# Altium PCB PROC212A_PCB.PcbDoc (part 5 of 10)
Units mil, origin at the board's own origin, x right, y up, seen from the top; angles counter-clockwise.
Board outline 3032.48 x 3598.78 mil, 4 copper layers (Top Layer, L2_GND1, L3_PWR1, Bottom Layer), stack 60.58 mil thick; 432 components, 310 nets, 7775 pads, 1236 vias.
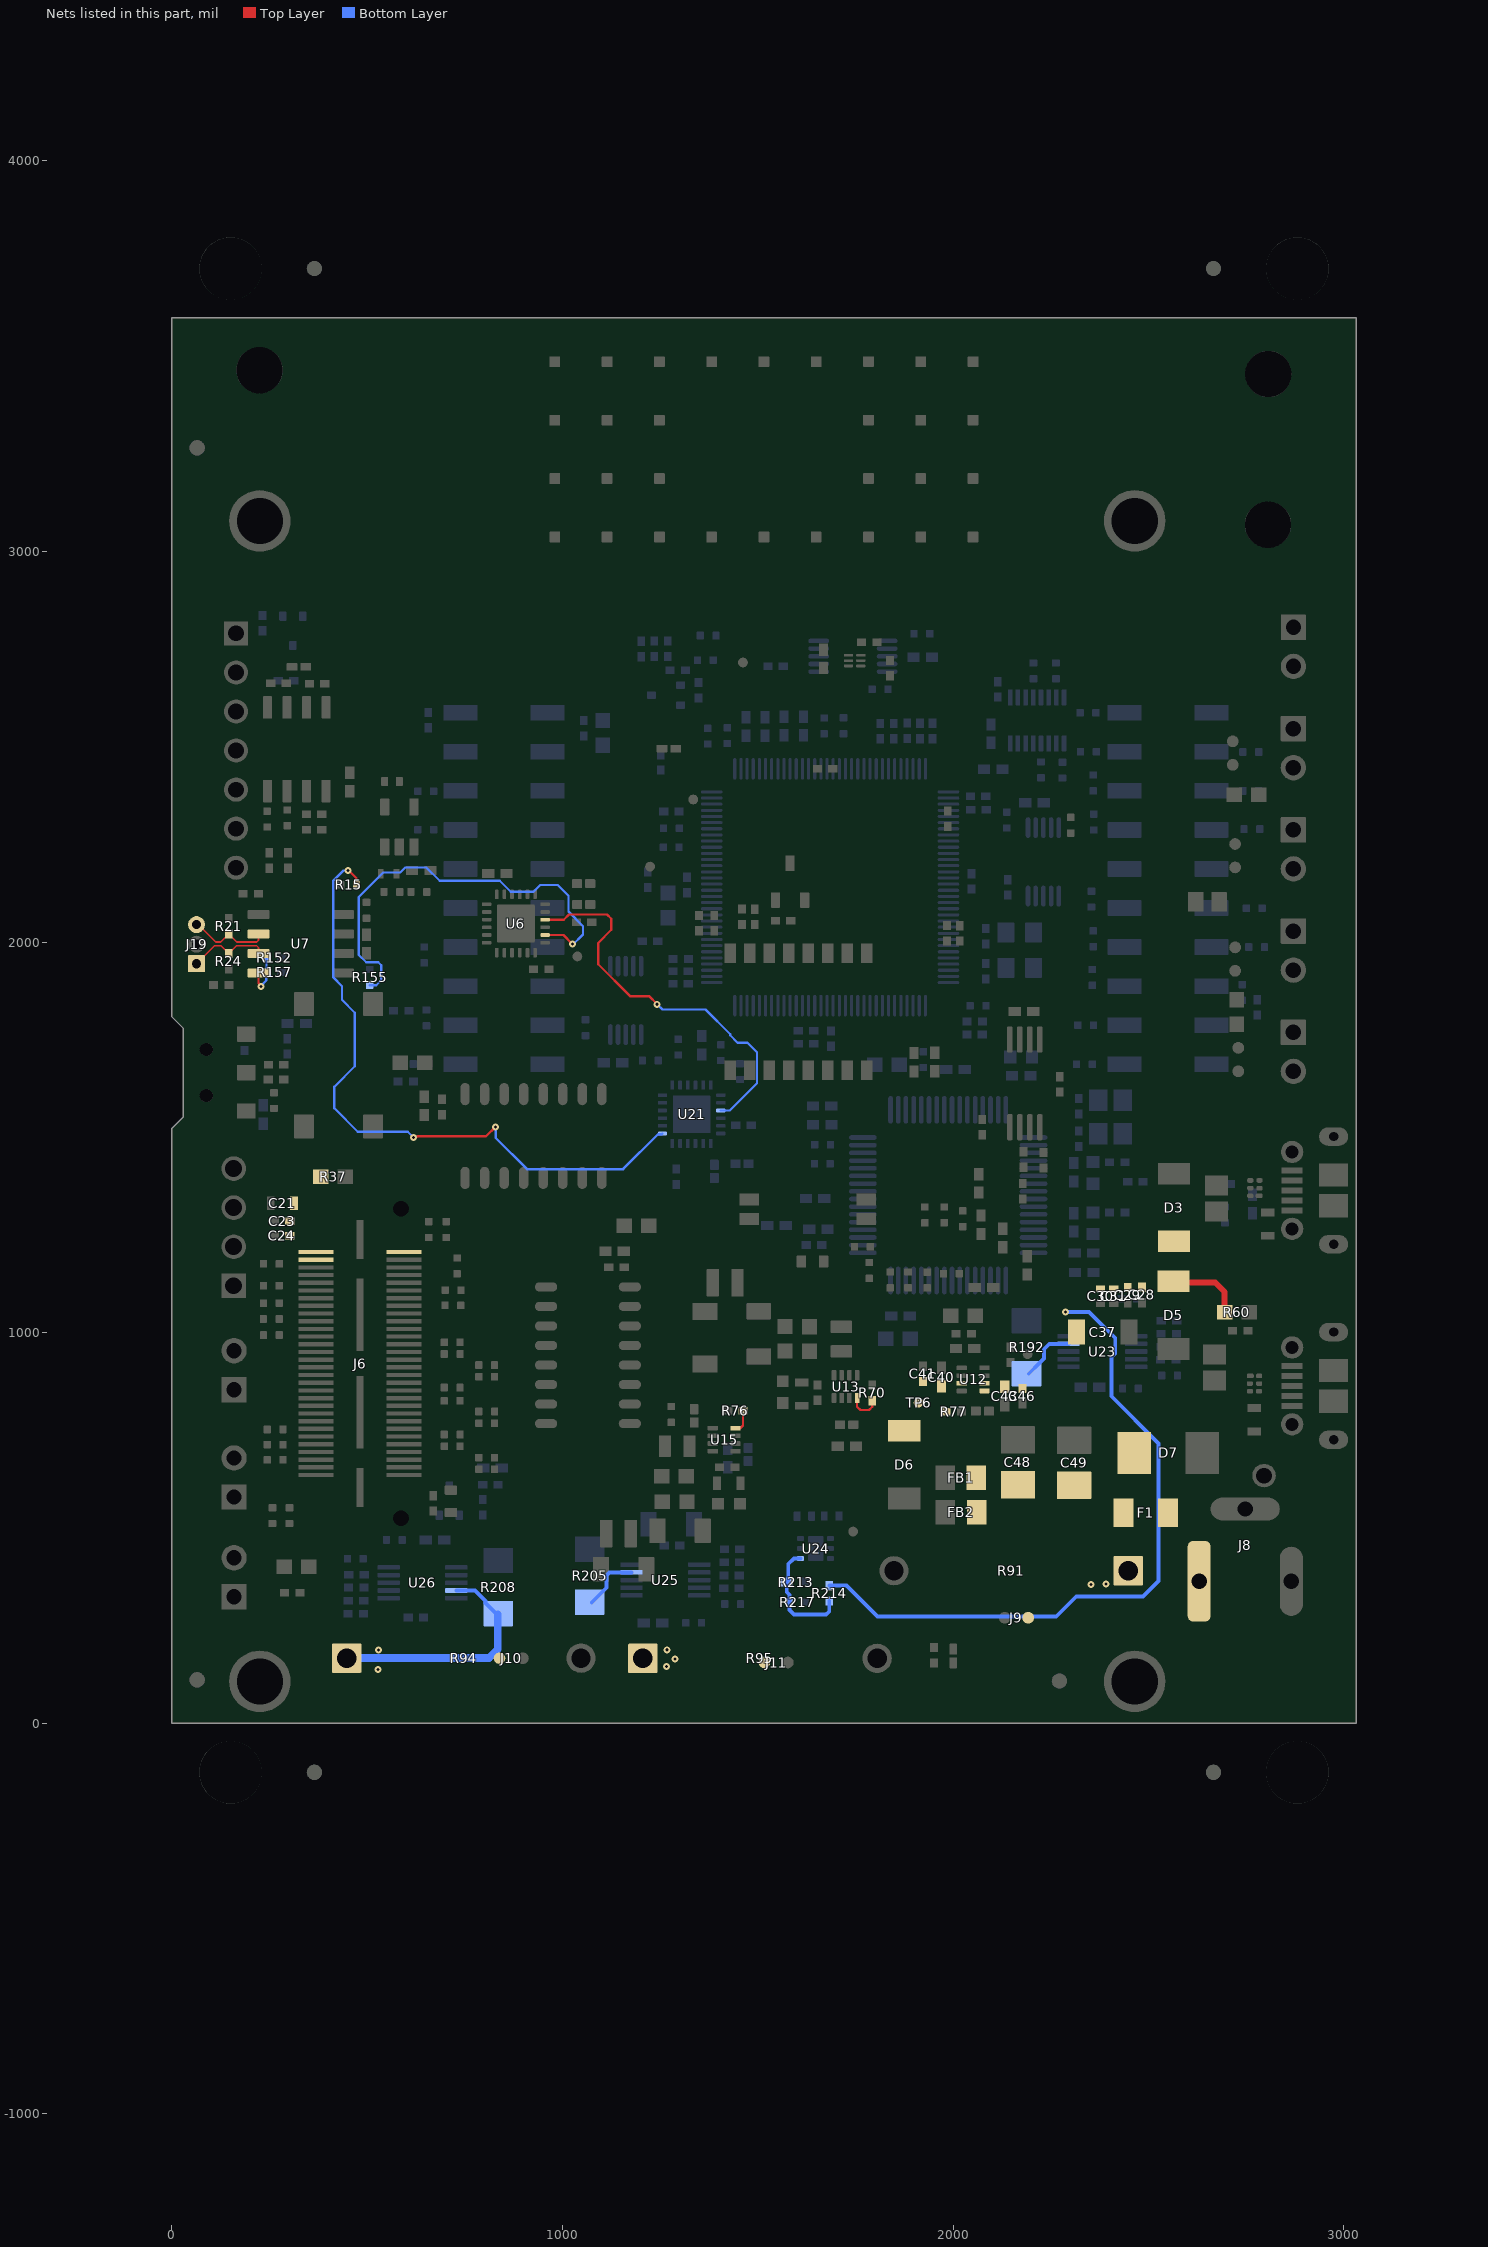
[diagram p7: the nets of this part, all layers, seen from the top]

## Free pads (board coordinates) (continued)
  round 5 on Mech16: 1(1216.41,2030.22) 1(1216.41,2030.22) 1(1216.41,2081.22) 1(1216.41,2081.22) 1(1227.66,2006.22) 1(1227.66,2006.22) 1(1227.66,2014.37) 1(1227.66,2014.37) 1(1227.66,2016.65) 1(1227.66,2016.65) 1(1227.66,2024.15) 1(1227.66,2024.15) 1(1227.66,2030.22) 1(1227.66,2030.22) 1(1236.69,1733.73) 1(1236.69,1733.73) 1(1236.69,1733.75) 1(1236.69,1733.75) 1(1236.69,1790.75) 1(1236.69,1790.75) 1(1236.69,1790.77) 1(1236.69,1790.77) 1(1239.68,1730.75) 1(1239.68,1730.75) 1(1239.68,1793.75) 1(1239.68,1793.75) 1(1245.16,2006.22) 1(1245.16,2006.22) 1(1245.16,2014.37) 1(1245.16,2014.37) 1(1245.16,2016.65) 1(1245.16,2016.65) 1(1245.16,2024.15) 1(1245.16,2024.15) 1(1245.16,2030.22) 1(1245.16,2030.22) 1(1249.31,1706.25) 1(1249.31,1706.25) 1(1249.31,1714.8) 1(1249.31,1714.8) 1(1249.31,1718.44) 1(1249.31,1718.44) 1(1249.31,1719.7) 1(1249.31,1719.7) 1(1249.31,1729.66) 1(1249.31,1729.66) 1(1249.31,1730.75) 1(1249.31,1730.75) 1(1249.31,1793.75) 1(1249.31,1793.75) 1(1249.31,1794.83) 1(1249.31,1794.83) 1(1249.31,1804.79) 1(1249.31,1804.79) 1(1249.31,1806.06) 1(1249.31,1806.06) 1(1249.31,1809.7) 1(1249.31,1809.7) 1(1249.31,1818.25) 1(1249.31,1818.25) 1(1264.07,1706.25) 1(1264.07,1706.25) 1(1264.07,1714.8) 1(1264.07,1714.8) 1(1264.07,1718.44) 1(1264.07,1718.44) 1(1264.07,1719.7) 1(1264.07,1719.7) 1(1264.07,1729.66) 1(1264.07,1729.66) 1(1264.07,1730.75) 1(1264.07,1730.75) 1(1264.07,1793.75) 1(1264.07,1793.75) 1(1264.07,1794.83) 1(1264.07,1794.83) 1(1264.07,1804.79) 1(1264.07,1804.79) 1(1264.07,1806.06) 1(1264.07,1806.06) 1(1264.07,1809.7) 1(1264.07,1809.7) 1(1264.07,1818.25) 1(1264.07,1818.25) 1(1265.16,2081.22) 1(1265.16,2081.22) 1(1265.16,2087.28) 1(1265.16,2087.28) 1(1265.16,2094.78) 1(1265.16,2094.78) 1(1265.16,2097.06) 1(1265.16,2097.06) 1(1265.16,2105.22) 1(1265.16,2105.22) 1(1282.66,2081.22) 1(1282.66,2081.22) 1(1282.66,2087.28) 1(1282.66,2087.28) 1(1282.66,2094.78) 1(1282.66,2094.78) 1(1282.66,2097.06) 1(1282.66,2097.06) 1(1282.66,2105.22) 1(1282.66,2105.22) 1(1286.81,1706.25) 1(1286.81,1706.25) 1(1286.81,1714.8) 1(1286.81,1714.8) 1(1286.81,1718.44) 1(1286.81,1718.44) 1(1286.81,1719.7) 1(1286.81,1719.7) 1(1286.81,1729.66) 1(1286.81,1729.66) 1(1286.81,1730.75) 1(1286.81,1730.75) 1(1286.81,1793.75) 1(1286.81,1793.75) 1(1286.81,1794.83) 1(1286.81,1794.83) 1(1286.81,1804.79) 1(1286.81,1804.79) 1(1286.81,1806.06) 1(1286.81,1806.06) 1(1286.81,1809.7) 1(1286.81,1809.7) 1(1286.81,1818.25) 1(1286.81,1818.25) 1(1301.57,1706.25) 1(1301.57,1706.25) 1(1301.57,1714.8) 1(1301.57,1714.8) 1(1301.57,1718.44) 1(1301.57,1718.44) 1(1301.57,1719.7) 1(1301.57,1719.7) 1(1301.57,1729.66) 1(1301.57,1729.66) 1(1301.57,1730.75) 1(1301.57,1730.75) 1(1301.57,1793.75) 1(1301.57,1793.75) 1(1301.57,1794.83) 1(1301.57,1794.83) 1(1301.57,1804.79) 1(1301.57,1804.79) 1(1301.57,1806.06) 1(1301.57,1806.06) 1(1301.57,1809.7) 1(1301.57,1809.7) 1(1301.57,1818.25) 1(1301.57,1818.25) 1(1302.66,2006.22) 1(1302.66,2006.22) 1(1302.66,2014.37) 1(1302.66,2014.37) 1(1302.66,2016.65) 1(1302.66,2016.65) 1(1302.66,2024.15) 1(1302.66,2024.15) 1(1302.66,2030.22) 1(1302.66,2030.22) 1(1320.16,2006.22) 1(1320.16,2006.22) 1(1320.16,2014.37) 1(1320.16,2014.37) 1(1320.16,2016.65) 1(1320.16,2016.65) 1(1320.16,2024.15) 1(1320.16,2024.15) 1(1320.16,2030.22) 1(1320.16,2030.22) 1(1324.31,1706.25) 1(1324.31,1706.25) 1(1324.31,1714.8) 1(1324.31,1714.8) 1(1324.31,1718.44) 1(1324.31,1718.44) 1(1324.31,1719.7) 1(1324.31,1719.7) 1(1324.31,1729.66) 1(1324.31,1729.66) 1(1324.31,1730.75) 1(1324.31,1730.75) 1(1324.31,1793.75) 1(1324.31,1793.75) 1(1324.31,1794.83) 1(1324.31,1794.83) 1(1324.31,1804.79) 1(1324.31,1804.79) 1(1324.31,1806.06) 1(1324.31,1806.06) 1(1324.31,1809.7) 1(1324.31,1809.7) 1(1324.31,1818.25) 1(1324.31,1818.25) 1(1330.43,1739.57) 1(1330.43,1739.57) 1(1330.43,1749.57) 1(1330.43,1749.57) 1(1331.41,2030.22) 1(1331.41,2030.22) 1(1331.41,2081.22) 1(1331.41,2081.22) 1(1339.07,1706.25) 1(1339.07,1706.25) 1(1339.07,1714.8) 1(1339.07,1714.8) 1(1339.07,1718.44) 1(1339.07,1718.44) 1(1339.07,1719.7) 1(1339.07,1719.7) 1(1339.07,1729.66) 1(1339.07,1729.66) 1(1339.07,1730.75) 1(1339.07,1730.75) 1(1339.07,1793.75) 1(1339.07,1793.75) 1(1339.07,1794.83) 1(1339.07,1794.83) 1(1339.07,1804.79) 1(1339.07,1804.79) 1(1339.07,1806.06) 1(1339.07,1806.06) 1(1339.07,1809.7) 1(1339.07,1809.7) 1(1339.07,1818.25) 1(1339.07,1818.25) 1(1348.69,1730.75) 1(1348.69,1730.75) 1(1348.69,1793.75) 1(1348.69,1793.75) 1(1351.69,1733.73) 1(1351.69,1733.73) 1(1351.69,1733.75) 1(1351.69,1733.75) 1(1351.69,1790.75) 1(1351.69,1790.75) 1(1351.69,1790.77) 1(1351.69,1790.77) 1(1455.43,-1057.06) 1(1455.43,-1057.06) 1(1457.76,-555.79) 1(1457.76,-555.79) 1(2048.06,1670.52) 1(2048.06,1670.52) 1(2048.06,1680.36) 1(2048.06,1680.36) 1(2048.06,1696.11) 1(2048.06,1696.11) 1(2048.06,1705.95) 1(2048.06,1705.95) 1(2048.06,1721.7) 1(2048.06,1721.7) 1(2048.06,1731.54) 1(2048.06,1731.54) 1(2048.06,1747.29) 1(2048.06,1747.29) 1(2048.06,1757.13) 1(2048.06,1757.13) 1(2059.87,1670.52) 1(2059.87,1670.52) 1(2059.87,1680.36) 1(2059.87,1680.36) 1(2059.87,1696.11) 1(2059.87,1696.11) 1(2059.87,1705.95) 1(2059.87,1705.95) 1(2059.87,1721.7) 1(2059.87,1721.7) 1(2059.87,1731.54) 1(2059.87,1731.54) 1(2059.87,1747.29) 1(2059.87,1747.29) 1(2059.87,1757.13) 1(2059.87,1757.13) 1(2065.3,1670.52) 1(2065.3,1670.52) 1(2065.3,1680.36) 1(2065.3,1680.36) 1(2065.3,1696.11) 1(2065.3,1696.11) 1(2065.3,1705.95) 1(2065.3,1705.95) 1(2065.3,1721.7) 1(2065.3,1721.7) 1(2065.3,1731.54) 1(2065.3,1731.54) 1(2065.3,1747.29) 1(2065.3,1747.29) 1(2065.3,1757.13) 1(2065.3,1757.13) 1(2070.52,1670.52) 1(2070.52,1670.52) 1(2070.52,1680.36) 1(2070.52,1680.36) 1(2070.52,1696.11) 1(2070.52,1696.11) 1(2070.52,1705.95) 1(2070.52,1705.95) 1(2070.52,1721.7) 1(2070.52,1721.7) 1(2070.52,1731.54) 1(2070.52,1731.54) 1(2070.52,1747.29) 1(2070.52,1747.29) 1(2070.52,1757.13) 1(2070.52,1757.13) 1(2079.56,1670.52) 1(2079.56,1670.52) 1(2079.56,1680.36) 1(2079.56,1680.36) 1(2079.56,1696.11) 1(2079.56,1696.11) 1(2079.56,1705.95) 1(2079.56,1705.95) 1(2079.56,1721.7) 1(2079.56,1721.7) 1(2079.56,1731.54) 1(2079.56,1731.54) 1(2079.56,1747.29) 1(2079.56,1747.29) 1(2079.56,1757.13) 1(2079.56,1757.13) 1(2085.46,1652.61) 1(2085.46,1652.61) 1(2085.46,1652.61) 1(2085.46,1670.52) 1(2085.46,1670.52) 1(2085.46,1680.36) 1(2085.46,1680.36) 1(2085.46,1696.11) 1(2085.46,1696.11) 1(2085.46,1705.95) 1(2085.46,1705.95) 1(2085.46,1721.7) 1(2085.46,1721.7) 1(2085.46,1731.54) 1(2085.46,1731.54) 1(2085.46,1747.29) 1(2085.46,1747.29) 1(2085.46,1757.13) 1(2085.46,1757.13) 1(2085.46,1774.65) 1(2085.46,1774.65) 1(2085.46,1774.65) 1(2089.23,1656.37) 1(2089.23,1656.37) 1(2089.23,1656.37) 1(2089.23,1770.89) 1(2089.23,1770.89) 1(2089.23,1770.89) 1(2104.02,1521.6) 1(2104.02,1521.6) 1(2104.02,1532.28) 1(2104.02,1532.28) 1(2104.02,1541.28) 1(2104.02,1541.28) 1(2104.02,1551.96) 1(2104.02,1551.96) 1(2104.02,1580.64) 1(2104.02,1580.64) 1(2104.02,1591.32) 1(2104.02,1591.32) 1(2104.02,1512.6) 1(2104.02,1512.6) 1(2104.02,1560.96) 1(2104.02,1560.96) 1(2104.02,1571.64) 1(2104.02,1571.64) 1(2104.02,1600.32) 1(2104.02,1600.32) 1(2105.15,1664.42) 1(2105.15,1664.42) 1(2105.15,1680.17) 1(2105.15,1680.17) 1(2113.45,1512.6) 1(2113.45,1512.6) 1(2113.45,1521.6) 1(2113.45,1521.6) 1(2113.45,1532.28) 1(2113.45,1532.28) 1(2113.45,1541.28) 1(2113.45,1541.28) 1(2113.45,1551.96) 1(2113.45,1551.96) 1(2113.45,1560.96) 1(2113.45,1560.96) 1(2113.45,1571.64) 1(2113.45,1571.64) 1(2113.45,1580.64) 1(2113.45,1580.64) 1(2113.45,1591.32) 1(2113.45,1591.32) 1(2113.45,1600.32) 1(2113.45,1600.32) 1(2118.17,1512.6) 1(2118.17,1512.6) 1(2118.17,1521.6) 1(2118.17,1521.6) 1(2118.17,1532.28) 1(2118.17,1532.28) 1(2118.17,1541.28) 1(2118.17,1541.28) 1(2118.17,1551.96) 1(2118.17,1551.96) 1(2118.17,1560.96) 1(2118.17,1560.96) 1(2118.17,1571.64) 1(2118.17,1571.64) 1(2118.17,1580.64) 1(2118.17,1580.64) 1(2118.17,1591.32) 1(2118.17,1591.32) 1(2118.17,1600.32) 1(2118.17,1600.32) 1(2118.3,1512.6) 1(2118.3,1512.6) 1(2118.3,1521.6) 1(2118.3,1521.6) 1(2118.3,1532.28) 1(2118.3,1532.28) 1(2118.3,1541.28) 1(2118.3,1541.28) 1(2118.3,1551.96) 1(2118.3,1551.96) 1(2118.3,1560.96) 1(2118.3,1560.96) 1(2118.3,1571.64) 1(2118.3,1571.64) 1(2118.3,1580.64) 1(2118.3,1580.64) 1(2118.3,1591.32) 1(2118.3,1591.32) 1(2118.3,1600.32) 1(2118.3,1600.32) 1(2130.26,1512.6) 1(2130.26,1512.6) 1(2130.26,1521.6) 1(2130.26,1521.6) 1(2130.26,1532.28) 1(2130.26,1532.28) 1(2130.26,1541.28) 1(2130.26,1541.28) 1(2130.26,1551.96) 1(2130.26,1551.96) 1(2130.26,1560.96) 1(2130.26,1560.96) 1(2130.26,1571.64) 1(2130.26,1571.64) 1(2130.26,1580.64) 1(2130.26,1580.64) 1(2130.26,1591.32) 1(2130.26,1591.32) 1(2130.26,1600.32) 1(2130.26,1600.32) 1(2141.52,1502.46) 1(2141.52,1502.46) 1(2141.52,1512.6) 1(2141.52,1512.6) 1(2141.52,1521.6) 1(2141.52,1521.6) 1(2141.52,1532.28) 1(2141.52,1532.28) 1(2141.52,1541.28) 1(2141.52,1541.28) 1(2141.52,1551.96) 1(2141.52,1551.96) 1(2141.52,1560.96) 1(2141.52,1560.96) 1(2141.52,1571.64) 1(2141.52,1571.64) 1(2141.52,1580.64) 1(2141.52,1580.64) 1(2141.52,1591.32) 1(2141.52,1591.32) 1(2141.52,1600.32) 1(2141.52,1600.32) 1(2141.52,1610.46) 1(2141.52,1610.46) 1(2141.52,1502.35) 1(2141.52,1502.35) 1(2141.52,1610.57) 1(2141.52,1610.57) 1(2142.6,735.54) 1(2142.6,735.54) 1(2142.6,815.54) 1(2142.6,815.54) 1(2142.6,1131.67) 1(2142.6,1131.67) 1(2142.6,1211.67) 1(2142.6,1211.67) 1(2146.41,1497.46) 1(2146.41,1497.46) 1(2146.41,1615.46) 1(2146.41,1615.46) 1(2146.52,1497.46) 1(2146.52,1497.46) 1(2146.52,1615.46) 1(2146.52,1615.46) 1(2148.52,1518.46) 1(2148.52,1518.46) 1(2162.33,385.38) 1(2162.33,385.38) 1(2162.33,396.06) 1(2162.33,396.06) 1(2162.33,405.06) 1(2162.33,405.06) 1(2162.33,415.74) 1(2162.33,415.74) 1(2162.33,444.42) 1(2162.33,444.42) 1(2162.33,455.1) 1(2162.33,455.1) 1(2162.33,376.38) 1(2162.33,376.38) 1(2162.33,424.74) 1(2162.33,424.74) 1(2162.33,435.42) 1(2162.33,435.42) 1(2162.33,464.1) 1(2162.33,464.1) 1(2171.76,376.38) 1(2171.76,376.38) 1(2171.76,385.38) 1(2171.76,385.38) 1(2171.76,396.06) 1(2171.76,396.06) 1(2171.76,405.06) 1(2171.76,405.06) 1(2171.76,415.74) 1(2171.76,415.74) 1(2171.76,424.74) 1(2171.76,424.74) 1(2171.76,435.42) 1(2171.76,435.42) 1(2171.76,444.42) 1(2171.76,444.42) 1(2171.76,455.1) 1(2171.76,455.1) 1(2171.76,464.1) 1(2171.76,464.1) 1(2176.48,376.38) 1(2176.48,376.38) 1(2176.48,385.38) 1(2176.48,385.38) 1(2176.48,396.06) 1(2176.48,396.06) 1(2176.48,405.06) 1(2176.48,405.06) 1(2176.48,415.74) 1(2176.48,415.74) 1(2176.48,424.74) 1(2176.48,424.74) 1(2176.48,435.42) 1(2176.48,435.42) 1(2176.48,444.42) 1(2176.48,444.42) 1(2176.48,455.1) 1(2176.48,455.1) 1(2176.48,464.1) 1(2176.48,464.1) 1(2176.52,1518.46) 1(2176.52,1518.46) 1(2176.61,376.38) 1(2176.61,376.38) 1(2176.61,385.38) 1(2176.61,385.38) 1(2176.61,396.06) 1(2176.61,396.06) 1(2176.61,405.06) 1(2176.61,405.06) 1(2176.61,415.74) 1(2176.61,415.74) 1(2176.61,424.74) 1(2176.61,424.74) 1(2176.61,435.42) 1(2176.61,435.42) 1(2176.61,444.42) 1(2176.61,444.42) 1(2176.61,455.1) 1(2176.61,455.1) 1(2176.61,464.1) 1(2176.61,464.1) 1(2188.56,376.38) 1(2188.56,376.38) 1(2188.56,385.38) 1(2188.56,385.38) 1(2188.56,396.06) 1(2188.56,396.06) 1(2188.56,405.06) 1(2188.56,405.06) 1(2188.56,415.74) 1(2188.56,415.74) 1(2188.56,424.74) 1(2188.56,424.74) 1(2188.56,435.42) 1(2188.56,435.42) 1(2188.56,444.42) 1(2188.56,444.42) 1(2188.56,455.1) 1(2188.56,455.1) 1(2188.56,464.1) 1(2188.56,464.1) 1(2199.83,366.24) 1(2199.83,366.24) 1(2199.83,376.38) 1(2199.83,376.38) 1(2199.83,385.38) 1(2199.83,385.38) 1(2199.83,396.06) 1(2199.83,396.06) 1(2199.83,405.06) 1(2199.83,405.06) 1(2199.83,415.74) 1(2199.83,415.74) 1(2199.83,424.74) 1(2199.83,424.74) 1(2199.83,435.42) 1(2199.83,435.42) 1(2199.83,444.42) 1(2199.83,444.42) 1(2199.83,455.1) 1(2199.83,455.1) 1(2199.83,464.1) 1(2199.83,464.1) 1(2199.83,474.24) 1(2199.83,474.24) 1(2199.83,366.13) 1(2199.83,366.13) 1(2199.83,474.35) 1(2199.83,474.35) 1(2204.72,361.24) 1(2204.72,361.24) 1(2204.72,479.24) 1(2204.72,479.24) 1(2204.83,361.24) 1(2204.83,361.24) 1(2204.83,479.24) 1(2204.83,479.24) 1(2206.83,382.24) 1(2206.83,382.24) 1(2234.83,382.24) 1(2234.83,382.24) 1(2254.52,1497.46) 1(2254.52,1497.46) 1(2254.52,1615.46) 1(2254.52,1615.46) 1(2254.63,1497.46) 1(2254.63,1497.46) 1(2254.63,1615.46) 1(2254.63,1615.46) 1(2258.86,1656.37) 1(2258.86,1656.37) 1(2258.86,1656.37) 1(2258.86,1770.89) 1(2258.86,1770.89) 1(2258.86,1770.89) 1(2259.52,1502.35) 1(2259.52,1502.35) 1(2259.52,1610.57) 1(2259.52,1610.57) 1(2259.52,1502.46) 1(2259.52,1502.46) 1(2259.52,1512.6) 1(2259.52,1512.6) 1(2259.52,1521.6) 1(2259.52,1521.6) 1(2259.52,1532.28) 1(2259.52,1532.28) 1(2259.52,1541.28) 1(2259.52,1541.28) 1(2259.52,1551.96) 1(2259.52,1551.96) 1(2259.52,1560.96) 1(2259.52,1560.96) 1(2259.52,1571.64) 1(2259.52,1571.64) 1(2259.52,1580.64) 1(2259.52,1580.64) 1(2259.52,1591.32) 1(2259.52,1591.32) 1(2259.52,1600.32) 1(2259.52,1600.32) 1(2259.52,1610.46) 1(2259.52,1610.46) 1(2262.63,1652.61) 1(2262.63,1652.61) 1(2262.63,1652.61) 1(2262.63,1670.52) 1(2262.63,1670.52) 1(2262.63,1680.36) 1(2262.63,1680.36) 1(2262.63,1696.11) 1(2262.63,1696.11) 1(2262.63,1705.95) 1(2262.63,1705.95) 1(2262.63,1721.7) 1(2262.63,1721.7) 1(2262.63,1731.54) 1(2262.63,1731.54) 1(2262.63,1747.29) 1(2262.63,1747.29) 1(2262.63,1757.13) 1(2262.63,1757.13) 1(2262.63,1774.65) 1(2262.63,1774.65) 1(2262.63,1774.65) 1(2268.53,1670.52) 1(2268.53,1670.52) 1(2268.53,1680.36) 1(2268.53,1680.36) 1(2268.53,1696.11) 1(2268.53,1696.11) 1(2268.53,1705.95) 1(2268.53,1705.95) 1(2268.53,1721.7) 1(2268.53,1721.7) 1(2268.53,1731.54) 1(2268.53,1731.54) 1(2268.53,1747.29) 1(2268.53,1747.29) 1(2268.53,1757.13) 1(2268.53,1757.13) 1(2270.78,1512.6) 1(2270.78,1512.6) 1(2270.78,1521.6) 1(2270.78,1521.6) 1(2270.78,1532.28) 1(2270.78,1532.28) 1(2270.78,1541.28) 1(2270.78,1541.28) 1(2270.78,1551.96) 1(2270.78,1551.96) 1(2270.78,1560.96) 1(2270.78,1560.96) 1(2270.78,1571.64) 1(2270.78,1571.64) 1(2270.78,1600.32) 1(2270.78,1600.32) 1(2270.78,1580.64) 1(2270.78,1580.64) 1(2270.78,1591.32) 1(2270.78,1591.32) 1(2277.58,1670.52) 1(2277.58,1670.52) 1(2277.58,1680.36) 1(2277.58,1680.36) 1(2277.58,1696.11) 1(2277.58,1696.11) 1(2277.58,1705.95) 1(2277.58,1705.95) 1(2277.58,1721.7) 1(2277.58,1721.7) 1(2277.58,1731.54) 1(2277.58,1731.54) 1(2277.58,1747.29) 1(2277.58,1747.29) 1(2277.58,1757.13) 1(2277.58,1757.13) 1(2282.74,1512.6) 1(2282.74,1512.6) 1(2282.74,1521.6) 1(2282.74,1521.6) 1(2282.74,1532.28) 1(2282.74,1532.28) 1(2282.74,1541.28) 1(2282.74,1541.28) 1(2282.74,1551.96) 1(2282.74,1551.96) 1(2282.74,1560.96) 1(2282.74,1560.96) 1(2282.74,1571.64) 1(2282.74,1571.64) 1(2282.74,1580.64) 1(2282.74,1580.64) 1(2282.74,1591.32) 1(2282.74,1591.32) 1(2282.74,1600.32) 1(2282.74,1600.32) 1(2282.79,1670.52) 1(2282.79,1670.52) 1(2282.79,1680.36) 1(2282.79,1680.36) 1(2282.79,1696.11) 1(2282.79,1696.11) 1(2282.79,1705.95) 1(2282.79,1705.95) 1(2282.79,1721.7) 1(2282.79,1721.7) 1(2282.79,1731.54) 1(2282.79,1731.54) 1(2282.79,1747.29) 1(2282.79,1747.29) 1(2282.79,1757.13) 1(2282.79,1757.13) 1(2282.87,1580.64) 1(2282.87,1580.64) 1(2282.87,1591.32) 1(2282.87,1591.32) 1(2282.87,1512.6) 1(2282.87,1512.6) 1(2282.87,1521.6) 1(2282.87,1521.6) 1(2282.87,1532.28) 1(2282.87,1532.28) 1(2282.87,1541.28) 1(2282.87,1541.28) 1(2282.87,1551.96) 1(2282.87,1551.96) 1(2282.87,1560.96) 1(2282.87,1560.96) 1(2282.87,1571.64) 1(2282.87,1571.64) 1(2282.87,1600.32) 1(2282.87,1600.32) 1(2287.59,1512.6) 1(2287.59,1512.6) 1(2287.59,1521.6) 1(2287.59,1521.6) 1(2287.59,1532.28) 1(2287.59,1532.28) 1(2287.59,1541.28) 1(2287.59,1541.28) 1(2287.59,1551.96) 1(2287.59,1551.96) 1(2287.59,1560.96) 1(2287.59,1560.96) 1(2287.59,1571.64) 1(2287.59,1571.64) 1(2287.59,1580.64) 1(2287.59,1580.64) 1(2287.59,1591.32) 1(2287.59,1591.32) 1(2287.59,1600.32) 1(2287.59,1600.32) 1(2288.22,1670.52) 1(2288.22,1670.52) 1(2288.22,1680.36) 1(2288.22,1680.36) 1(2288.22,1696.11) 1(2288.22,1696.11) 1(2288.22,1705.95) 1(2288.22,1705.95) 1(2288.22,1721.7) 1(2288.22,1721.7) 1(2288.22,1731.54) 1(2288.22,1731.54) 1(2288.22,1747.29) 1(2288.22,1747.29) 1(2288.22,1757.13) 1(2288.22,1757.13) 1(2288.6,1131.67) 1(2288.6,1131.67) 1(2288.6,1211.67) 1(2288.6,1211.67) 1(2290.6,735.54) 1(2290.6,735.54) 1(2290.6,735.67) 1(2290.6,735.67) 1(2290.6,815.54) 1(2290.6,815.54) 1(2290.6,815.67) 1(2290.6,815.67) 1(2290.6,1131.67) 1(2290.6,1131.67) 1(2290.6,1211.67) 1(2290.6,1211.67) 1(2297.02,1512.6) 1(2297.02,1512.6) 1(2297.02,1521.6) 1(2297.02,1521.6) 1(2297.02,1532.28) 1(2297.02,1532.28) 1(2297.02,1541.28) 1(2297.02,1541.28) 1(2297.02,1551.96) 1(2297.02,1551.96) 1(2297.02,1560.96) 1(2297.02,1560.96) 1(2297.02,1571.64) 1(2297.02,1571.64) 1(2297.02,1580.64) 1(2297.02,1580.64) 1(2297.02,1591.32) 1(2297.02,1591.32) 1(2297.02,1600.32) 1(2297.02,1600.32) 1(2300.03,1670.52) 1(2300.03,1670.52) 1(2300.03,1680.36) 1(2300.03,1680.36) 1(2300.03,1696.11) 1(2300.03,1696.11) 1(2300.03,1705.95) 1(2300.03,1705.95) 1(2300.03,1721.7) 1(2300.03,1721.7) 1(2300.03,1731.54) 1(2300.03,1731.54) 1(2300.03,1747.29) 1(2300.03,1747.29) 1(2300.03,1757.13) 1(2300.03,1757.13) 1(2312.83,361.24) 1(2312.83,361.24) 1(2312.83,479.24) 1(2312.83,479.24) 1(2312.93,361.24) 1(2312.93,361.24) 1(2312.93,479.24) 1(2312.93,479.24) 1(2317.82,366.13) 1(2317.82,366.13) 1(2317.82,474.35) 1(2317.82,474.35) 1(2317.83,366.24) 1(2317.83,366.24) 1(2317.83,376.38) 1(2317.83,376.38) 1(2317.83,385.38) 1(2317.83,385.38) 1(2317.83,396.06) 1(2317.83,396.06) 1(2317.83,405.06) 1(2317.83,405.06) 1(2317.83,415.74) 1(2317.83,415.74) 1(2317.83,424.74) 1(2317.83,424.74) 1(2317.83,435.42) 1(2317.83,435.42) 1(2317.83,444.42) 1(2317.83,444.42) 1(2317.83,455.1) 1(2317.83,455.1) 1(2317.83,464.1) 1(2317.83,464.1) 1(2317.83,474.24) 1(2317.83,474.24) 1(2329.09,376.38) 1(2329.09,376.38) 1(2329.09,385.38) 1(2329.09,385.38) 1(2329.09,396.06) 1(2329.09,396.06) 1(2329.09,405.06) 1(2329.09,405.06) 1(2329.09,415.74) 1(2329.09,415.74) 1(2329.09,424.74) 1(2329.09,424.74) 1(2329.09,435.42) 1(2329.09,435.42) 1(2329.09,464.1) 1(2329.09,464.1) 1(2329.09,444.42) 1(2329.09,444.42) 1(2329.09,455.1) 1(2329.09,455.1) 1(2341.04,376.38) 1(2341.04,376.38) 1(2341.04,385.38) 1(2341.04,385.38) 1(2341.04,396.06) 1(2341.04,396.06) 1(2341.04,405.06) 1(2341.04,405.06) 1(2341.04,415.74) 1(2341.04,415.74) 1(2341.04,424.74) 1(2341.04,424.74) 1(2341.04,435.42) 1(2341.04,435.42) 1(2341.04,444.42) 1(2341.04,444.42) 1(2341.04,455.1) 1(2341.04,455.1) 1(2341.04,464.1) 1(2341.04,464.1) 1(2341.17,444.42) 1(2341.17,444.42) 1(2341.17,455.1) 1(2341.17,455.1) 1(2341.17,376.38) 1(2341.17,376.38) 1(2341.17,385.38) 1(2341.17,385.38) 1(2341.17,396.06) 1(2341.17,396.06) 1(2341.17,405.06) 1(2341.17,405.06) 1(2341.17,415.74) 1(2341.17,415.74) 1(2341.17,424.74) 1(2341.17,424.74) 1(2341.17,435.42) 1(2341.17,435.42) 1(2341.17,464.1) 1(2341.17,464.1) 1(2345.89,376.38) 1(2345.89,376.38) 1(2345.89,385.38) 1(2345.89,385.38) 1(2345.89,396.06) 1(2345.89,396.06) 1(2345.89,405.06) 1(2345.89,405.06) 1(2345.89,415.74) 1(2345.89,415.74) 1(2345.89,424.74) 1(2345.89,424.74) 1(2345.89,435.42) 1(2345.89,435.42) 1(2345.89,444.42) 1(2345.89,444.42) 1(2345.89,455.1) 1(2345.89,455.1) 1(2345.89,464.1) 1(2345.89,464.1) 1(2355.33,376.38) 1(2355.33,376.38) 1(2355.33,385.38) 1(2355.33,385.38) 1(2355.33,396.06) 1(2355.33,396.06) 1(2355.33,405.06) 1(2355.33,405.06) 1(2355.33,415.74) 1(2355.33,415.74) 1(2355.33,424.74) 1(2355.33,424.74) 1(2355.33,435.42) 1(2355.33,435.42) 1(2355.33,444.42) 1(2355.33,444.42) 1(2355.33,455.1) 1(2355.33,455.1) 1(2355.33,464.1) 1(2355.33,464.1) 1(2355.43,-1057.06) 1(2355.43,-1057.06) 1(2357.76,-555.79) 1(2357.76,-555.79) 1(2436.6,1131.67) 1(2436.6,1131.67) 1(2436.6,1211.67) 1(2436.6,1211.67) 1(2438.6,735.67) 1(2438.6,735.67) 1(2438.6,815.67) 1(2438.6,815.67) 1(2470.05,-1026.56) 1(2470.05,-1026.56) 1(2470.05,-1017.57) 1(2470.05,-1017.57) 1(2470.05,-878.56) 1(2470.05,-878.56) 1(2470.05,-869.56) 1(2470.05,-869.56) 1(2622.21,591.86) 1(2622.21,591.86) 1(2622.21,600.86) 1(2622.21,600.86) 1(2622.21,611.54) 1(2622.21,611.54) 1(2622.21,620.54) 1(2622.21,620.54) 1(2622.21,631.22) 1(2622.21,631.22) 1(2622.21,640.22) 1(2622.21,640.22) 1(2622.21,650.9) 1(2622.21,650.9) 1(2622.21,659.9) 1(2622.21,659.9) 1(2622.21,670.58) 1(2622.21,670.58) 1(2622.21,679.58) 1(2622.21,679.58) 1(2631.64,591.86) 1(2631.64,591.86) 1(2631.64,600.86) 1(2631.64,600.86) 1(2631.64,611.54) 1(2631.64,611.54) 1(2631.64,620.54) 1(2631.64,620.54) 1(2631.64,631.22) 1(2631.64,631.22) 1(2631.64,640.22) 1(2631.64,640.22) 1(2631.64,650.9) 1(2631.64,650.9) 1(2631.64,659.9) 1(2631.64,659.9) 1(2631.64,670.58) 1(2631.64,670.58) 1(2631.64,679.58) 1(2631.64,679.58) 1(2636.36,591.86) 1(2636.36,591.86) 1(2636.36,600.86) 1(2636.36,600.86) 1(2636.36,611.54) 1(2636.36,611.54) 1(2636.36,620.54) 1(2636.36,620.54) 1(2636.36,631.22) 1(2636.36,631.22) 1(2636.36,640.22) 1(2636.36,640.22) 1(2636.36,650.9) 1(2636.36,650.9) 1(2636.36,659.9) 1(2636.36,659.9) 1(2636.36,670.58) 1(2636.36,670.58) 1(2636.36,679.58) 1(2636.36,679.58) 1(2636.49,591.86) 1(2636.49,591.86) 1(2636.49,600.86) 1(2636.49,600.86) 1(2636.49,611.54) 1(2636.49,611.54) 1(2636.49,620.54) 1(2636.49,620.54) 1(2636.49,631.22) 1(2636.49,631.22) 1(2636.49,640.22) 1(2636.49,640.22) 1(2636.49,650.9) 1(2636.49,650.9) 1(2636.49,659.9) 1(2636.49,659.9) 1(2636.49,670.58) 1(2636.49,670.58) 1(2636.49,679.58) 1(2636.49,679.58) 1(2648.45,591.86) 1(2648.45,591.86) 1(2648.45,600.86) 1(2648.45,600.86) 1(2648.45,611.54) 1(2648.45,611.54) 1(2648.45,620.54) 1(2648.45,620.54) 1(2648.45,631.22) 1(2648.45,631.22) 1(2648.45,640.22) 1(2648.45,640.22) 1(2648.45,650.9) 1(2648.45,650.9) 1(2648.45,659.9) 1(2648.45,659.9) 1(2648.45,670.58) 1(2648.45,670.58) 1(2648.45,679.58) 1(2648.45,679.58) 1(2659.71,581.72) 1(2659.71,581.72) 1(2659.71,591.86) 1(2659.71,591.86) 1(2659.71,600.86) 1(2659.71,600.86) 1(2659.71,611.54) 1(2659.71,611.54) 1(2659.71,620.54) 1(2659.71,620.54) 1(2659.71,631.22) 1(2659.71,631.22) 1(2659.71,640.22) 1(2659.71,640.22) 1(2659.71,650.9) 1(2659.71,650.9) 1(2659.71,659.9) 1(2659.71,659.9) 1(2659.71,670.58) 1(2659.71,670.58) 1(2659.71,679.58) 1(2659.71,679.58) 1(2659.71,689.72) 1(2659.71,689.72) 1(2659.71,581.61) 1(2659.71,581.61) 1(2659.71,689.83) 1(2659.71,689.83) 1(2660.75,-800.73) 1(2660.75,-800.73) 1(2660.75,-652.73) 1(2660.75,-652.73) 1(2664.6,576.72) 1(2664.6,576.72) 1(2664.6,694.72) 1(2664.6,694.72) 1(2664.71,576.72) 1(2664.71,576.72) 1(2664.71,694.72) 1(2664.71,694.72) 1(2737.05,-1026.56) 1(2737.05,-869.56) 1(2740.75,-800.73) 1(2740.75,-800.73) 1(2740.75,-652.73) 1(2740.75,-652.73) 1(2742.71,673.72) 1(2742.71,673.72) 1(2750.75,-800.73) 1(2750.75,-800.73) 1(2750.75,-652.73) 1(2750.75,-652.73) 1(2770.71,673.72) 1(2770.71,673.72) 1(2772.71,576.72) 1(2772.71,576.72) 1(2772.71,694.72) 1(2772.71,694.72) 1(2772.82,576.72) 1(2772.82,576.72) 1(2772.82,694.72) 1(2772.82,694.72) 1(2777.71,581.61) 1(2777.71,581.61) 1(2777.71,689.83) 1(2777.71,689.83) 1(2777.71,581.72) 1(2777.71,581.72) 1(2777.71,591.86) 1(2777.71,591.86) 1(2777.71,600.86) 1(2777.71,600.86) 1(2777.71,611.54) 1(2777.71,611.54) 1(2777.71,620.54) 1(2777.71,620.54) 1(2777.71,631.22) 1(2777.71,631.22) 1(2777.71,640.22) 1(2777.71,640.22) 1(2777.71,650.9) 1(2777.71,650.9) 1(2777.71,659.9) 1(2777.71,659.9) 1(2777.71,670.58) 1(2777.71,670.58) 1(2777.71,679.58) 1(2777.71,679.58) 1(2777.71,689.72) 1(2777.71,689.72) 1(2788.97,591.86) 1(2788.97,591.86) 1(2788.97,600.86) 1(2788.97,600.86) 1(2788.97,611.54) 1(2788.97,611.54) 1(2788.97,620.54) 1(2788.97,620.54) 1(2788.97,631.22) 1(2788.97,631.22) 1(2788.97,640.22) 1(2788.97,640.22) 1(2788.97,650.9) 1(2788.97,650.9) 1(2788.97,659.9) 1(2788.97,659.9) 1(2788.97,670.58) 1(2788.97,670.58) 1(2788.97,679.58) 1(2788.97,679.58) 1(2800.92,591.86) 1(2800.92,591.86) 1(2800.92,600.86) 1(2800.92,600.86) 1(2800.92,611.54) 1(2800.92,611.54) 1(2800.92,620.54) 1(2800.92,620.54) 1(2800.92,631.22) 1(2800.92,631.22) 1(2800.92,640.22) 1(2800.92,640.22) 1(2800.92,650.9) 1(2800.92,650.9) 1(2800.92,659.9) 1(2800.92,659.9) 1(2800.92,670.58) 1(2800.92,670.58) 1(2800.92,679.58) 1(2800.92,679.58) 1(2801.05,591.86) 1(2801.05,591.86) 1(2801.05,600.86) 1(2801.05,600.86) 1(2801.05,611.54) 1(2801.05,611.54) 1(2801.05,620.54) 1(2801.05,620.54) 1(2801.05,631.22) 1(2801.05,631.22) 1(2801.05,640.22) 1(2801.05,640.22) 1(2801.05,650.9) 1(2801.05,650.9) 1(2801.05,659.9) 1(2801.05,659.9) 1(2801.05,670.58) 1(2801.05,670.58) 1(2801.05,679.58) 1(2801.05,679.58) 1(2805.77,591.86) 1(2805.77,591.86) 1(2805.77,600.86) 1(2805.77,600.86) 1(2805.77,611.54) 1(2805.77,611.54) 1(2805.77,620.54) 1(2805.77,620.54) 1(2805.77,631.22) 1(2805.77,631.22) 1(2805.77,640.22) 1(2805.77,640.22) 1(2805.77,650.9) 1(2805.77,650.9) 1(2805.77,659.9) 1(2805.77,659.9) 1(2805.77,670.58) 1(2805.77,670.58) 1(2805.77,679.58) 1(2805.77,679.58) 1(2815.21,591.86) 1(2815.21,591.86) 1(2815.21,600.86) 1(2815.21,600.86) 1(2815.21,611.54) 1(2815.21,611.54) 1(2815.21,620.54) 1(2815.21,620.54) 1(2815.21,631.22) 1(2815.21,631.22) 1(2815.21,640.22) 1(2815.21,640.22) 1(2815.21,650.9) 1(2815.21,650.9) 1(2815.21,659.9) 1(2815.21,659.9) 1(2815.21,670.58) 1(2815.21,670.58) 1(2815.21,679.58) 1(2815.21,679.58) 1(2830.75,-800.73) 1(2830.75,-800.73) 1(2830.75,-652.73) 1(2830.75,-652.73) 1(2900.75,3007.27) 1(2900.75,3007.27) 1(2900.75,3155.27) 1(2900.75,3155.27) 1(2980.75,3007.27) 1(2980.75,3007.27) 1(2980.75,3155.27) 1(2980.75,3155.27) 1(3017.66,2113.96) 1(3017.66,2113.96) 1(3017.66,2133.64) 1(3017.66,2133.64) 1(3017.66,2153.92) 1(3017.66,2153.92) 1(3017.66,2176.95) 1(3017.66,2176.95) 1(3017.66,2271.44) 1(3017.66,2271.44) 1(3017.66,2294.47) 1(3017.66,2294.47) 1(3017.66,2314.74) 1(3017.66,2314.74) 1(3017.66,2334.43) 1(3017.66,2334.43) 1(3017.66,2788.96) 1(3017.66,2788.96) 1(3017.66,2808.64) 1(3017.66,2808.64) 1(3017.66,2828.92) 1(3017.66,2828.92) 1(3017.66,2851.95) 1(3017.66,2851.95) 1(3017.66,2946.44) 1(3017.66,2946.44) 1(3017.66,2969.47) 1(3017.66,2969.47) 1(3017.66,2989.74) 1(3017.66,2989.74) 1(3017.66,3009.43) 1(3017.66,3009.43) 1(3029.47,2076.55) 1(3029.47,2076.55) 1(3029.47,2098.21) 1(3029.47,2098.21) 1(3029.47,2113.96) 1(3029.47,2113.96) 1(3029.47,2334.43) 1(3029.47,2334.43) 1(3029.47,2350.18) 1(3029.47,2350.18) 1(3029.47,2371.83) 1(3029.47,2371.83) 1(3029.47,2751.55) 1(3029.47,2751.55) 1(3029.47,2773.21) 1(3029.47,2773.21) 1(3029.47,2788.96) 1(3029.47,2788.96) 1(3029.47,3009.43) 1(3029.47,3009.43) 1(3029.47,3025.18) 1(3029.47,3025.18) 1(3029.47,3046.83) 1(3029.47,3046.83) 1(3214.51,2076.55) 1(3214.51,2076.55) 1(3214.51,2076.55) 1(3214.51,2088.37) 1(3214.51,2098.21) 1(3214.51,2098.21) 1(3214.51,2098.21) 1(3214.51,2350.18) 1(3214.51,2350.18) 1(3214.51,2350.18) 1(3214.51,2360.02) 1(3214.51,2371.83) 1(3214.51,2371.83) 1(3214.51,2371.83) 1(3214.51,2751.55) 1(3214.51,2751.55) 1(3214.51,2751.55) 1(3214.51,2763.37) 1(3214.51,2773.21) 1(3214.51,2773.21) 1(3214.51,2773.21) 1(3214.51,3025.18) 1(3214.51,3025.18) 1(3214.51,3025.18) 1(3214.51,3035.02) 1(3214.51,3046.83) 1(3214.51,3046.83) 1(3214.51,3046.83) 1(3214.64,2088.37) 1(3214.64,2360.02) 1(3214.64,2763.37) 1(3214.64,3035.02) 1(3214.64,2088.37) 1(3214.64,2360.02) 1(3214.64,2763.37) 1(3214.64,3035.02) 1(3217.3,2098.21) 1(3217.3,2098.21) 1(3217.3,2098.21) 1(3217.3,2350.18) 1(3217.3,2350.18) 1(3217.3,2350.18) 1(3217.3,2773.21) 1(3217.3,2773.21) 1(3217.3,2773.21) 1(3217.3,3025.18) 1(3217.3,3025.18) 1(3217.3,3025.18) 1(3217.45,2069.97) 1(3217.45,2069.97) 1(3217.45,2378.42) 1(3217.45,2378.42) 1(3217.45,2744.97) 1(3217.45,2744.97) 1(3217.45,3053.42) 1(3217.45,3053.42) 1(3217.54,2350.17) 1(3217.54,2350.17) 1(3217.54,3025.17) 1(3217.54,3025.17) 1(3217.64,2098.23) 1(3217.64,2098.23) 1(3217.64,2773.23) 1(3217.64,2773.23) 1(3217.79,2350.14) 1(3217.79,2350.14) 1(3217.79,3025.14) 1(3217.79,3025.14) 1(3217.89,2098.27) 1(3217.89,2098.27) 1(3217.89,2773.27) 1(3217.89,2773.27) 1(3218.03,2350.09) 1(3218.03,2350.09) 1(3218.03,3025.09) 1(3218.03,3025.09) 1(3218.13,2098.32) 1(3218.13,2098.32) 1(3218.13,2773.32) 1(3218.13,2773.32) 1(3218.27,2350.02) 1(3218.27,2350.02) 1(3218.27,3025.02) 1(3218.27,3025.02) 1(3218.37,2098.4) 1(3218.37,2098.4) 1(3218.37,2773.4) 1(3218.37,2773.4) 1(3218.51,2349.93) 1(3218.51,2349.93) 1(3218.51,3024.93) 1(3218.51,3024.93) 1(3218.61,2098.5) 1(3218.61,2098.5) 1(3218.61,2773.5) 1(3218.61,2773.5) 1(3218.75,2349.83) 1(3218.75,2349.83) 1(3218.75,3024.83) 1(3218.75,3024.83) 1(3218.85,2098.61) 1(3218.85,2098.61) 1(3218.85,2773.61) 1(3218.85,2773.61) 1(3218.98,2349.7) 1(3218.98,2349.7) 1(3218.98,3024.7) 1(3218.98,3024.7) 1(3219.08,2098.74) 1(3219.08,2098.74) 1(3219.08,2773.74) 1(3219.08,2773.74) 1(3219.21,2349.56) 1(3219.21,2349.56) 1(3219.21,3024.56) 1(3219.21,3024.56) 1(3219.3,2098.9) 1(3219.3,2098.9) 1(3219.3,2773.9) 1(3219.3,2773.9) 1(3219.43,2349.39) 1(3219.43,2349.39) 1(3219.43,3024.39) 1(3219.43,3024.39) 1(3219.52,2099.07) 1(3219.52,2099.07) 1(3219.52,2774.07) 1(3219.52,2774.07) 1(3219.65,2349.21) 1(3219.65,2349.21) 1(3219.65,3024.21) 1(3219.65,3024.21) 1(3219.74,2099.25) 1(3219.74,2099.25) 1(3219.74,2774.25) 1(3219.74,2774.25) 1(3219.86,2349.02) 1(3219.86,2349.02) 1(3219.86,3024.02) 1(3219.86,3024.02) 1(3219.95,2099.46) 1(3219.95,2099.46) 1(3219.95,2774.46) 1(3219.95,2774.46) 1(3220.07,2348.8) 1(3220.07,2348.8) 1(3220.07,3023.8) 1(3220.07,3023.8) 1(3220.15,2099.68) 1(3220.15,2099.68) 1(3220.15,2774.68) 1(3220.15,2774.68) 1(3220.27,2348.57) 1(3220.27,2348.57) 1(3220.27,3023.57) 1(3220.27,3023.57) 1(3220.35,2099.91) 1(3220.35,2099.91) 1(3220.35,2774.91) 1(3220.35,2774.91) 1(3220.46,2348.33) 1(3220.46,2348.33) 1(3220.46,3023.33) 1(3220.46,3023.33) 1(3220.54,2100.17) 1(3220.54,2100.17) 1(3220.54,2775.17) 1(3220.54,2775.17) 1(3220.64,2348.06) 1(3220.64,2348.06) 1(3220.64,3023.06) 1(3220.64,3023.06) 1(3220.65,2062.78) 1(3220.65,2062.78) 1(3220.65,2385.61) 1(3220.65,2385.61) 1(3220.65,2737.78) 1(3220.65,2737.78) 1(3220.65,3060.61) 1(3220.65,3060.61) 1(3220.72,2100.43) 1(3220.72,2100.43) 1(3220.72,2775.43) 1(3220.72,2775.43) 1(3220.82,2347.79) 1(3220.82,2347.79) 1(3220.82,3022.79) 1(3220.82,3022.79) 1(3220.89,2100.72) 1(3220.89,2100.72) 1(3220.89,2775.72) 1(3220.89,2775.72) 1(3220.99,2347.5) 1(3220.99,2347.5) 1(3220.99,3022.5) 1(3220.99,3022.5) 1(3221.05,2101.01) 1(3221.05,2101.01) 1(3221.05,2776.01) 1(3221.05,2776.01) 1(3221.14,2347.2) 1(3221.14,2347.2) 1(3221.14,3022.2) 1(3221.14,3022.2) 1(3221.21,2101.32) 1(3221.21,2101.32) 1(3221.21,2776.32) 1(3221.21,2776.32) 1(3221.29,2346.88) 1(3221.29,2346.88) 1(3221.29,3021.88) 1(3221.29,3021.88) 1(3221.35,2101.64) 1(3221.35,2101.64) 1(3221.35,2776.64) 1(3221.35,2776.64) 1(3221.43,2346.56) 1(3221.43,2346.56) 1(3221.43,3021.56) 1(3221.43,3021.56) 1(3221.48,2101.97) 1(3221.48,2101.97) 1(3221.48,2776.97) 1(3221.48,2776.97) 1(3221.56,2346.22) 1(3221.56,2346.22) 1(3221.56,3021.22) 1(3221.56,3021.22) 1(3221.61,2102.31) 1(3221.61,2102.31) 1(3221.61,2777.31) 1(3221.61,2777.31) 1(3221.67,2345.87) 1(3221.67,2345.87) 1(3221.67,3020.87) 1(3221.67,3020.87) 1(3221.72,2102.66) 1(3221.72,2102.66) 1(3221.72,2777.66) 1(3221.72,2777.66) 1(3221.78,2345.52) 1(3221.78,2345.52) 1(3221.78,3020.52) 1(3221.78,3020.52) 1(3221.82,2103.02) 1(3221.82,2103.02) 1(3221.82,2778.02) 1(3221.82,2778.02) 1(3221.87,2345.16) 1(3221.87,2345.16) 1(3221.87,3020.16) 1(3221.87,3020.16) 1(3221.91,2103.38) 1(3221.91,2103.38) 1(3221.91,2778.38) 1(3221.91,2778.38) 1(3221.96,2344.79) 1(3221.96,2344.79) 1(3221.96,3019.79) 1(3221.96,3019.79) 1(3221.99,2103.76) 1(3221.99,2103.76) 1(3221.99,2778.76) 1(3221.99,2778.76) 1(3222.03,2344.41) 1(3222.03,2344.41) 1(3222.03,3019.41) 1(3222.03,3019.41) 1(3222.06,2104.13) 1(3222.06,2104.13) 1(3222.06,2779.13) 1(3222.06,2779.13) 1(3222.09,2344.03) 1(3222.09,2344.03) 1(3222.09,3019.03) 1(3222.09,3019.03) 1(3222.11,2104.52) 1(3222.11,2104.52) 1(3222.11,2779.52) 1(3222.11,2779.52) 1(3222.14,2343.64) 1(3222.14,2343.64) 1(3222.14,3018.64) 1(3222.14,3018.64) 1(3222.15,2104.91) 1(3222.15,2104.91) 1(3222.15,2779.91) 1(3222.15,2779.91) 1(3222.17,2343.25) 1(3222.17,2343.25) 1(3222.17,3018.25) 1(3222.17,3018.25) 1(3222.18,2105.3) 1(3222.18,2105.3) 1(3222.18,2780.3) 1(3222.18,2780.3) 1(3222.2,2342.86) 1(3222.2,2342.86) 1(3222.2,3017.86) 1(3222.2,3017.86) 1(3222.2,2105.69) 1(3222.2,2105.69) 1(3222.2,2780.69) 1(3222.2,2780.69) 1(3222.21,2106.08) 1(3222.21,2106.08) 1(3222.21,2342.3) 1(3222.21,2342.3) 1(3222.21,2781.08) 1(3222.21,2781.08) 1(3222.21,3017.3) 1(3222.21,3017.3) 1(3225.25,2081.48) 1(3225.25,2366.91) 1(3225.25,2756.48) 1(3225.25,3041.91) 1(3225.25,2081.48) 1(3225.25,2366.91) 1(3225.25,2756.48) 1(3225.25,3041.91) 1(3226.53,2098.21) 1(3226.53,2098.21) 1(3226.53,2350.18) 1(3226.53,2350.18) 1(3226.53,2773.21) 1(3226.53,2773.21) 1(3226.53,3025.18) 1(3226.53,3025.18) 1(3226.77,2350.17) 1(3226.77,2350.17) 1(3226.77,3025.17) 1(3226.77,3025.17) 1(3226.88,2098.23) 1(3226.88,2098.23) 1(3226.88,2773.23) 1(3226.88,2773.23) 1(3227.02,2350.14) 1(3227.02,2350.14) 1(3227.02,3025.14) 1(3227.02,3025.14) 1(3227.12,2098.27) 1(3227.12,2098.27) 1(3227.12,2773.27) 1(3227.12,2773.27) 1(3227.26,2350.09) 1(3227.26,2350.09) 1(3227.26,3025.09) 1(3227.26,3025.09) 1(3227.36,2098.32) 1(3227.36,2098.32) 1(3227.36,2773.32) 1(3227.36,2773.32) 1(3227.5,2350.02) 1(3227.5,2350.02) 1(3227.5,3025.02) 1(3227.5,3025.02) 1(3227.6,2098.4) 1(3227.6,2098.4) 1(3227.6,2773.4) 1(3227.6,2773.4) 1(3227.74,2349.93) 1(3227.74,2349.93) 1(3227.74,3024.93) 1(3227.74,3024.93) 1(3227.84,2098.5) 1(3227.84,2098.5) 1(3227.84,2773.5) 1(3227.84,2773.5) 1(3227.98,2349.83) 1(3227.98,2349.83) 1(3227.98,3024.83) 1(3227.98,3024.83) 1(3228.08,2098.61) 1(3228.08,2098.61) 1(3228.08,2773.61) 1(3228.08,2773.61) 1(3228.21,2349.7) 1(3228.21,2349.7) 1(3228.21,3024.7) 1(3228.21,3024.7) 1(3228.23,2074.78) 1(3228.23,2074.78) 1(3228.23,2373.61) 1(3228.23,2373.61) 1(3228.23,2749.78) 1(3228.23,2749.78) 1(3228.23,3048.61) 1(3228.23,3048.61) 1(3228.31,2098.74) 1(3228.31,2098.74) 1(3228.31,2773.74) 1(3228.31,2773.74) 1(3228.44,2349.56) 1(3228.44,2349.56) 1(3228.44,3024.56) 1(3228.44,3024.56) 1(3228.53,2098.9) 1(3228.53,2098.9) 1(3228.53,2773.9) 1(3228.53,2773.9) 1(3228.66,2349.39) 1(3228.66,2349.39) 1(3228.66,3024.39) 1(3228.66,3024.39) 1(3228.76,2099.07) 1(3228.76,2099.07) 1(3228.76,2774.07) 1(3228.76,2774.07) 1(3228.88,2349.21) 1(3228.88,2349.21) 1(3228.88,3024.21) 1(3228.88,3024.21) 1(3228.97,2099.25) 1(3228.97,2099.25) 1(3228.97,2774.25) 1(3228.97,2774.25) 1(3229.1,2349.02) 1(3229.1,2349.02) 1(3229.1,3024.02) 1(3229.1,3024.02) 1(3229.18,2099.46) 1(3229.18,2099.46) 1(3229.18,2774.46) 1(3229.18,2774.46) 1(3229.3,2348.8) 1(3229.3,2348.8) 1(3229.3,3023.8) 1(3229.3,3023.8) 1(3229.39,2099.68) 1(3229.39,2099.68) 1(3229.39,2774.68) 1(3229.39,2774.68) 1(3229.5,2348.57) 1(3229.5,2348.57) 1(3229.5,3023.57) 1(3229.5,3023.57) 1(3229.58,2099.91) 1(3229.58,2099.91) 1(3229.58,2774.91) 1(3229.58,2774.91) 1(3229.69,2348.33) 1(3229.69,2348.33) 1(3229.69,3023.33) 1(3229.69,3023.33) 1(3229.77,2100.17) 1(3229.77,2100.17) 1(3229.77,2775.17) 1(3229.77,2775.17) 1(3229.88,2348.06) 1(3229.88,2348.06) 1(3229.88,3023.06) 1(3229.88,3023.06) 1(3229.95,2100.43) 1(3229.95,2100.43) 1(3229.95,2775.43) 1(3229.95,2775.43) 1(3230.05,2347.79) 1(3230.05,2347.79) 1(3230.05,3022.79) 1(3230.05,3022.79) 1(3230.12,2100.72) 1(3230.12,2100.72) 1(3230.12,2775.72) 1(3230.12,2775.72) 1(3230.22,2347.5) 1(3230.22,2347.5) 1(3230.22,3022.5) 1(3230.22,3022.5) 1(3230.28,2101.01) 1(3230.28,2101.01) 1(3230.28,2776.01) 1(3230.28,2776.01) 1(3230.38,2347.2) 1(3230.38,2347.2) 1(3230.38,3022.2) 1(3230.38,3022.2) 1(3230.44,2101.32) 1(3230.44,2101.32) 1(3230.44,2776.32) 1(3230.44,2776.32) 1(3230.52,2346.88) 1(3230.52,2346.88) 1(3230.52,3021.88) 1(3230.52,3021.88) 1(3230.58,2101.64) 1(3230.58,2101.64) 1(3230.58,2776.64) 1(3230.58,2776.64) 1(3230.66,2346.56) 1(3230.66,2346.56) 1(3230.66,3021.56) 1(3230.66,3021.56) 1(3230.72,2101.97) 1(3230.72,2101.97) 1(3230.72,2776.97) 1(3230.72,2776.97) 1(3230.79,2346.22) 1(3230.79,2346.22) 1(3230.79,3021.22) 1(3230.79,3021.22) 1(3230.84,2102.31) 1(3230.84,2102.31) 1(3230.84,2777.31) 1(3230.84,2777.31) 1(3230.91,2345.87) 1(3230.91,2345.87) 1(3230.91,3020.87) 1(3230.91,3020.87) 1(3230.95,2102.66) 1(3230.95,2102.66) 1(3230.95,2777.66) 1(3230.95,2777.66) 1(3231.01,2345.52) 1(3231.01,2345.52) 1(3231.01,3020.52) 1(3231.01,3020.52) 1(3231.05,2103.02) 1(3231.05,2103.02) 1(3231.05,2778.02) 1(3231.05,2778.02) 1(3231.11,2345.16) 1(3231.11,2345.16) 1(3231.11,3020.16) 1(3231.11,3020.16) 1(3231.14,2103.38) 1(3231.14,2103.38) 1(3231.14,2778.38) 1(3231.14,2778.38) 1(3231.19,2344.79) 1(3231.19,2344.79) 1(3231.19,3019.79) 1(3231.19,3019.79) 1(3231.22,2103.76) 1(3231.22,2103.76) 1(3231.22,2778.76) 1(3231.22,2778.76) 1(3231.26,2344.41) 1(3231.26,2344.41) 1(3231.26,3019.41) 1(3231.26,3019.41) 1(3231.29,2104.13) 1(3231.29,2104.13) 1(3231.29,2779.13) 1(3231.29,2779.13) 1(3231.32,2344.03) 1(3231.32,2344.03) 1(3231.32,3019.03) 1(3231.32,3019.03) 1(3231.34,2104.52) 1(3231.34,2104.52) 1(3231.34,2779.52) 1(3231.34,2779.52) 1(3231.37,2343.64) 1(3231.37,2343.64) 1(3231.37,3018.64) 1(3231.37,3018.64) 1(3231.38,2104.91) 1(3231.38,2104.91) 1(3231.38,2779.91) 1(3231.38,2779.91) 1(3231.4,2343.25) 1(3231.4,2343.25) 1(3231.4,3018.25) 1(3231.4,3018.25) 1(3231.42,2105.3) 1(3231.42,2105.3) 1(3231.42,2780.3) 1(3231.42,2780.3) 1(3231.43,2342.86) 1(3231.43,2342.86) 1(3231.43,3017.86) 1(3231.43,3017.86) 1(3231.43,2105.69) 1(3231.43,2105.69) 1(3231.43,2780.69) 1(3231.43,2780.69) 1(3231.44,2067.58) 1(3231.44,2067.58) 1(3231.44,2106.08) 1(3231.44,2106.08) 1(3231.44,2342.3) 1(3231.44,2342.3) 1(3231.44,2380.8) 1(3231.44,2380.8) 1(3231.44,2742.58) 1(3231.44,2742.58) 1(3231.44,2781.08) 1(3231.44,2781.08) 1(3231.44,3017.3) 1(3231.44,3017.3) 1(3231.44,3055.8) 1(3231.44,3055.8)
  round 61.02 on Mech16: 1(1244.38,-144.78) 1(1244.38,-44.78) 1(1310.75,448.27) 1(1310.75,548.27) 1(1421.38,1664.22) 1(1421.38,1764.22) 1(2300.75,2533.27) 1(2300.75,2633.27) 1(2813.75,1818.27) 1(2813.75,1918.27)
  round 140 on Mech16: 1(1259.4,3815.35)
  round 9.84 on Mech16: 1(1549.25,1943.73) 1(1559.1,1943.73) 1(2008.43,1676.62) 1(2016.93,1676.62) 1(2099.1,1516.54) 1(2099.1,1536.22) 1(2099.1,1595.28) 1(2099.1,1555.91) 1(2099.1,1575.59) 1(2134.53,1516.54) 1(2134.53,1536.22) 1(2134.53,1595.28) 1(2134.53,1555.91) 1(2134.53,1575.59) 1(2157.4,380.31) 1(2157.4,400) 1(2157.4,459.05) 1(2157.4,419.68) 1(2157.4,439.37) 1(2192.84,380.31) 1(2192.84,400) 1(2192.84,459.05) 1(2192.84,419.68) 1(2192.84,439.37) 1(2266.42,1555.91) 1(2266.42,1575.59) 1(2266.42,1516.54) 1(2266.42,1536.22) 1(2266.42,1595.28) 1(2301.85,1555.91) 1(2301.85,1575.59) 1(2301.85,1516.54) 1(2301.85,1536.22) 1(2301.85,1595.28) 1(2324.73,419.68) 1(2324.73,439.37) 1(2324.73,380.31) 1(2324.73,400) 1(2324.73,459.05) 1(2360.16,419.68) 1(2360.16,439.37) 1(2360.16,380.31) 1(2360.16,400) 1(2360.16,459.05) 1(2617.37,596.9) 1(2617.37,616.59) 1(2617.37,636.27) 1(2617.37,655.96) 1(2617.37,675.64) 1(2652.81,596.9) 1(2652.81,616.59) 1(2652.81,636.27) 1(2652.81,655.96) 1(2652.81,675.64) 1(2784.7,596.9) 1(2784.7,616.59) 1(2784.7,636.27) 1(2784.7,655.96) 1(2784.7,675.64) 1(2820.13,596.9) 1(2820.13,616.59) 1(2820.13,636.27) 1(2820.13,655.96) 1(2820.13,675.64) 1(2860.59,2210.5) 1(2894.1,2855.42)
  round 19.69 on Mech16: 1(1554.18,1943.73)
  round 27.56 on Mech16: 1(1592.56,1974.04)
  round 23.62 on Mech16: 1(1612.25,2005.54) 1(1635.87,2005.54) 1(2231.98,903.45)
  round 47.24 on Mech16: 1(1624.06,2005.54) 1(3116.59,2085.81) 1(3116.59,2361.41) 1(3116.59,2760.81) 1(3116.59,3036.41) 1(3144.15,2085.81) 1(3144.15,2361.41) 1(3144.15,2760.81) 1(3144.15,3036.41)
  round 125.2 on Mech16: 1(1657.76,-805.79) 1(2157.76,-805.79)
  round 8 on Mech16: 1(1813.38,1507.93) 1(1813.38,1538.27) 1(1969.1,1264.47) 1(1969.1,1264.47) 1(1976.55,1204.61) 1(1976.55,1271.92) 1(1976.55,1271.92) 1(1978.18,1271.92) 1(1985.63,1264.47) 1(1985.63,1264.47)
  round 6.89 on Mech16: 1(2032.81,1671.8) 1(2032.81,1678.69) 1(2032.81,1697.39) 1(2032.81,1704.28) 1(2032.81,1722.98) 1(2032.81,1729.87) 1(2032.81,1748.57) 1(2032.81,1755.46) 1(2092.85,1671.8) 1(2092.85,1678.69) 1(2092.85,1697.39) 1(2092.85,1704.28) 1(2092.85,1722.98) 1(2092.85,1729.87) 1(2092.85,1748.57) 1(2092.85,1755.46) 1(2257.22,1671.8) 1(2257.22,1678.69) 1(2257.22,1697.39) 1(2257.22,1704.28) 1(2257.22,1722.98) 1(2257.22,1729.87) 1(2257.22,1748.57) 1(2257.22,1755.46) 1(2317.25,1671.8) 1(2317.25,1678.69) 1(2317.25,1697.39) 1(2317.25,1704.28) 1(2317.25,1722.98) 1(2317.25,1729.87) 1(2317.25,1748.57) 1(2317.25,1755.46)
  round 6.69 on Mech16: 1(2098.79,657.86) 1(2098.79,681.49) 1(2105.02,1265.86) 1(2105.02,1289.49) 1(2193.28,657.86) 1(2193.28,681.49) 1(2199.51,1265.86) 1(2199.51,1289.49) 1(2204.71,580.88) 1(2204.71,651.74) 1(2207.89,1295.88) 1(2207.89,1366.74) 1(2283.45,580.88) 1(2283.45,651.74) 1(2286.63,1295.88) 1(2286.63,1366.74) 1(2296.71,582.88) 1(2296.71,653.74) 1(2296.89,1294.88) 1(2296.89,1365.74) 1(2375.45,582.88) 1(2375.45,653.74) 1(2375.63,1294.88) 1(2375.63,1365.74) 1(2387.36,1265.86) 1(2387.36,1289.49) 1(2388.36,657.86) 1(2388.36,681.49) 1(2481.85,1265.86) 1(2481.85,1289.49) 1(2482.85,657.86) 1(2482.85,681.49)
  round 2.76 on Mech16: 1(2102.73,616.52) 1(2102.73,616.52) 1(2102.73,722.82) 1(2102.73,722.82) 1(2108.96,1224.52) 1(2108.96,1224.52) 1(2108.96,1330.82) 1(2108.96,1330.82) 1(2189.34,616.52) 1(2189.34,616.52) 1(2189.34,722.82) 1(2189.34,722.82) 1(2195.57,1224.52) 1(2195.57,1224.52) 1(2195.57,1330.82) 1(2195.57,1330.82) 1(2206.68,547.41) 1(2206.68,547.41) 1(2206.68,685.21) 1(2206.68,685.21) 1(2209.86,1262.41) 1(2209.86,1262.41) 1(2209.86,1400.21) 1(2209.86,1400.21) 1(2281.48,547.41) 1(2281.48,547.41) 1(2281.48,685.21) 1(2281.48,685.21) 1(2284.66,1262.41) 1(2284.66,1262.41) 1(2284.66,1400.21) 1(2284.66,1400.21) 1(2298.68,549.41) 1(2298.68,549.41) 1(2298.68,687.21) 1(2298.68,687.21) 1(2298.86,1261.41) 1(2298.86,1261.41) 1(2298.86,1399.21) 1(2298.86,1399.21) 1(2373.48,549.41) 1(2373.48,549.41) 1(2373.48,687.21) 1(2373.48,687.21) 1(2373.66,1261.41) 1(2373.66,1261.41) 1(2373.66,1399.21) 1(2373.66,1399.21) 1(2391.29,1224.52) 1(2391.29,1224.52) 1(2391.29,1330.82) 1(2391.29,1330.82) 1(2392.29,616.52) 1(2392.29,616.52) 1(2392.29,722.82) 1(2392.29,722.82) 1(2477.91,1224.52) 1(2477.91,1224.52) 1(2477.91,1330.82) 1(2477.91,1330.82) 1(2478.91,616.52) 1(2478.91,616.52) 1(2478.91,722.82) 1(2478.91,722.82)
  round 21.42 on Mech16: 1(2212.58,2181.52)
  round 3.15 on Mech16: 1(2227.42,2062.03) 1(2227.42,2062.03) 1(2227.42,2164.4) 1(2227.42,2164.4) 1(2241.2,2144.71) 1(2256.95,2144.71) 1(2357.34,2062.03) 1(2357.34,2062.03) 1(2357.34,2164.4) 1(2357.34,2164.4)
  round 18.9 on Mech16: 1(2249.07,2144.71)
  round 74 on Mech16: 1(2638.88,1105.15)
  round 26.34 on Mech16: 1(2669.13,1519.94)
  round 80 on Mech16: 1(2686.75,-267.73)
  round 69.78 on Mech16: 1(2760.28,323.75)
  round 22.01 on Mech16: 1(2853.22,2166.22)
  round 1.97 on Mech16: 1(2856.65,2210.5) 1(2864.52,2210.5) 1(2890.16,2855.42) 1(2898.04,2855.42)
  round 29.53 on Mech16: 1(2875.36,-685.35) 1(2875.36,-508.19) 1(2904.89,-685.35) 1(2904.89,-508.19)
  round 59.06 on Mech16: 1(2949.18,-411.73) 1(3067.29,-411.73) 1(3126.34,-655.82) 1(3126.34,-537.71)
  round 20.19 on Mech16: 1(2996.85,2275.67) 1(2996.85,2950.67)
  round 33.46 on Mech16: 1(3009.65,-165.31) 1(3009.65,-131.85) 1(3009.65,279.69) 1(3009.65,313.15) 1(3043.11,-165.31) 1(3043.11,-131.85) 1(3043.11,279.69) 1(3043.11,313.15)
  round 66.93 on Mech16: 1(3026.38,-10.78) 1(3026.38,127.01) 1(3026.38,434.22) 1(3026.38,572.01)
  round 30.12 on Mech16: 1(3073.32,1270.16) 1(3073.32,1300.27) 1(3103.44,1270.16) 1(3103.44,1300.27)
  round 118.11 hole 118.11 unplated: 3(224.34,3464) 3(2806.34,3068.7) 3(2807.13,3454.52)
  round 157.48 hole 118.11: TH2(2465.13,106.94) TH9(225.13,3078.17) TH9(225.13,106.94) TH9(2465.12,3078.51)
  round 160 hole 160 unplated: ""(150,3724.51) ""(150.02,-125.73) ""(2881.47,3724.51) ""(2881.48,-125.73)

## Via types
v1: diameter 18, hole 8, Top Layer to Bottom Layer, tented both sides, 1224 vias
v2: diameter 19.68, hole 7.87, Top Layer to Bottom Layer, tented both sides, 10 vias
v3: diameter 19.68, hole 7.87, Top Layer to Bottom Layer, 2 vias

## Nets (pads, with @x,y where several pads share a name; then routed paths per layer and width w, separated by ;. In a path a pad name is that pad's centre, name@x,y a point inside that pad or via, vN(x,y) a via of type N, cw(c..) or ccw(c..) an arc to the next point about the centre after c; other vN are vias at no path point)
3V3_IO_SNS: J10.1 R94.1 R208.2 U26.9 | length 621
  Bottom Layer w10: U26.9@728.08,339.83 776.3,339.83 787.38,328.75 787.38,328.35 802.52,313.21 802.52,308.14 830,280.66 R208.2@835.51,280.66
  Bottom Layer w20: R94.1@447.49,166.61 811.42,166.61 834.04,189.23 R208.2@834.04,279.19
  other v1: 527.83,137.58 529.11,187.75
3V3_LDO_EN: R213.2 R214.1 R217.1 U24.4 | length 296.5
  Bottom Layer w10: U24.4@1609.67,421.76 1592.35,421.76 1577.91,407.32 1577.91,365.1 R213.2@1574.15,361.34 1574.15,335.91 1581.04,329.02 R217.1@1581.04,309.52 1581.04,289.64 1592.59,278.09 1674.71,278.09 1683.05,286.43 R214.1@1683.05,312.88
3V3_MODULE_SNS: J11.1 R95.1 R205.2 U25.9 | length 158.5
  Bottom Layer w10: R205.2@1074.95,309.58 1112.18,346.8 1112.18,378.26 1120.16,386.24 U25.9@1176.87,386.24
  Bottom Layer w12: R95.1@1205.59,166.11 R95.1@1210.14,161.56
  other v1: 1266.45,144.78 1288.39,164.47 1267.38,188.01
5V_DC: C48.1 C49.1 D7.1 F1.1 FB1.1 FB2.1
5V_IN_USB: C28.2 C29.1 C30.1 C31.2 C37.1 C43.2 C46.1 D3.1 D5.1 R60.2 R214.2 U12.6 | length 1937.9
  Top Layer w15: D5.1@2564.37,1131.4 2567.36,1128.41 2671.14,1128.41 2695.12,1104.43 R60.2@2695.12,1052.4
  Bottom Layer w10: R214.2@1683.05,352.25 1727.56,352.25 1806.17,273.63 2264.23,273.63 2315.36,324.77 2486.76,324.77 2526.15,364.16 2526.15,716.44 2405.31,837.28 2405.31,937.09 2415.31,947.09 2415.31,985.81 2347.87,1053.25 v1(2288.32,1053.25)
5V_JACK_IN: C40.2 C41.1 D6.1 R77.1 TP6.1 U12.3 U12.5
5V_SNS: J9.1 R91.1 R192.2 U23.9 | length 147.8
  Bottom Layer w10: R192.2@2193.68,894.7 2221.16,922.18 2221.16,922.3 2232.4,933.53 2232.4,957.54 2246.21,971.36 U23.9@2295.6,971.36
  other v1: 2353.31,355.09 2391.31,356.09
CAN_FD_RX: R15.2 U21.19 | length 1704
  Top Layer w5.9: v1(450.93,2183.4) 452.97,2183.4 472.07,2164.29 472.07,2147.27 R15.2@472.63,2146.71 ; v1(618.2,1499.46) 620.51,1501.77 626.71,1501.77 627.7,1502.77 804.36,1502.77 v1@828.41,1526.82
  Bottom Layer w5.9: v1(450.93,2183.4) 439.08,2183.4 413.31,2157.62 413.31,1909.09 435.31,1887.1 435.31,1852.09 468.31,1819.09 468.31,1682.09 415.89,1629.68 415.89,1574.51 475.75,1514.65 603.97,1514.65 618.2,1500.42 v1(618.2,1499.46) ; v1(828.71,1526.82) 828.71,1499.12 909.13,1418.69 1155.2,1418.69 1244.48,1507.97 1253.98,1507.97 U21.19@1255.75,1509.75
CAN_FD_RX_SPI_RS232_CTRL_GPIO_3: U6.22 U21.9 | length 1012.7
  Top Layer w5.9: U6.22@955.53,2057.42 1003.24,2057.42 1016.53,2070.7 1114.21,2070.7 1125.07,2059.84 1125.07,2031.57 1091.36,1997.85 1091.36,1943.06 1172.74,1861.68 1221.38,1861.68 v1(1242.35,1840.7)
  Bottom Layer w5.9: v1(1242.35,1840.7) 1255.88,1827.17 1365.86,1827.17 1429.22,1763.8 1429.22,1761.5 1448.37,1742.36 1473.7,1742.36 1498.1,1717.96 1498.1,1638.53 1428.38,1568.8 U21.9@1405.36,1568.8
CAN_FD_TX: R155.2 U6.20 | length 1135
  Top Layer w5.9: U6.20@955.53,2018.05 1002.41,2018.05 v1(1025.18,1995.27)
  Bottom Layer w5.9: R155.2@506.32,1889.6 522.83,1889.6 535.95,1902.73 535.95,1940.45 528.31,1948.09 497.31,1948.09 478.31,1967.09 478.31,2115.09 541.31,2178.09 584.31,2178.09 597.31,2191.09 651.31,2191.09 685.41,2156.99 839.2,2156.99 867.48,2128.71 925.41,2128.71 942.87,2146.17 987.62,2146.17 1015.31,2118.48 1015.31,2078.09 1052.69,2040.71 1052.69,2019.44 v1@1025.18,1991.93
CAN_STB: R152.2 R157.1 U7.8 | length 116.7
  Top Layer w5.9: U7.8@221.65,1920.7 221.65,1895.59 227.68,1889.56 v1(227.68,1886.29)
  Bottom Layer w5.9: v1(227.68,1886.29) 227.68,1887.79 241.63,1901.75 R157.1@241.63,1922.72 241.98,1923.07 R152.2@241.98,1960.2
CANH: J19.1 R24.2 U7.7 | length 212.3
  Top Layer w4: J19.1@62.99,1944.72 109.43,1991.15 124.89,1991.15 R24.2@145.33,1970.7 165.78,1991.15 200.6,1991.15 216.56,1991.15 221.65,1986.06 U7.7@221.65,1970.7
CANL: J19.3 R21.1 U7.6 | length 211.8
  Top Layer w4: J19.3@62.99,2044.72 67.49,2044.72 111.95,2000.25 124.89,2000.25 R21.1@145.34,2020.7 165.78,2000.25 196.83,2000.25 217.13,2000.25 221.65,2004.78 U7.6@221.65,2020.7
COMP1: R76.2 U15.4 | length 57.4
  Top Layer w5.9: U15.4@1443.1,755.53 1455.51,755.53 1461.94,761.96 R76.2@1461.94,797.88
COMP3: R70.2 U13.4 | length 84
  Top Layer w5.9: U13.4@1754.21,832.68 1754.21,810.47 1762.82,801.87 1784.87,801.87 1793.3,810.3 R70.2@1793.3,825.92
CONN_5V: C21.2 C23.1 C24.1 J6.1 J6.2 J6.3 R37.2
DC_JACK_5V: F1.2 J8.1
